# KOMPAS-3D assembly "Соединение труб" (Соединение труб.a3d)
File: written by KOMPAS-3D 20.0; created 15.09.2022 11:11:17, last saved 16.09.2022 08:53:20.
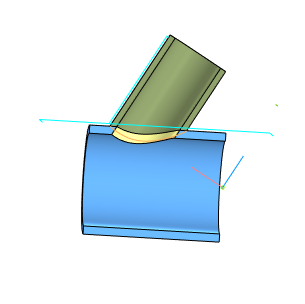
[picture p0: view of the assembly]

Document properties: Полное имя файла: D:\YAKOVLEV\ПРОЕКТЫ\ДЦ-2. ДП-7 Газопровод Окожушивание\ПРОБА Соединение труб. Окожушивание\ПРОБА 2\Соединение труб.a3d

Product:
- Part/product: Соединение труб
    Масса: 21154.1
  - unknown [Обозначение сварного шва]: Обозначение стандартного шва по ГОСТ
      additional columns: 0; 1; 1; 4.2507; 4.2507; 0.327589; 1; Длина, сечение шва и плотность наплавленного материала
  - Component [detail]: Вставка  | Материал: Сталь 45  ГОСТ 1050-2013 (density 7810 kg/m3); Масса: 5221.4; source file: Вставка.m3d
  - Component [detail]: Труба  | Материал: Сталь 45  ГОСТ 1050-2013 (density 7810 kg/m3); Масса: 15932.7; source file: Труба.m3d

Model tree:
1. Введите текст обозначения...  (labels: {F8D7F836-C962-4DAC-9A52-ED5B9D430847})
2. Обозначение стандартного шва по ГОСТ:1  (with: Обечайка:1)  (labels: {B79062AB-18CA-4C2C-A874-8D817D118EDE}; Обозначение стандартного шва по ГОСТ; OBJ2D_HIDDEN; {B8F93724-DA15-4186-B3D0-1CAD93540E6C})
     Длина линии сварного шва = 4250.7; Длина сварного шва = 4250.7; Масса* наплавленного материала = 0.327589
3. Смещенная плоскость:1
     Расстояние = 1800; Ориентация = 2; Ориентация = 2

Referenced files in D:\YAKOVLEV\ПРОЕКТЫ\ДЦ-2. ДП-7 Газопровод Окожушивание\ПРОБА Соединение труб. Окожушивание\ПРОБА 2\: Труба.m3d, Вставка.m3d
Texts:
  Welding3DConfiguration
  Точка начала. Х
  Точка начала. Y
  Точка начала. Z
  Обозначения сварных швов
